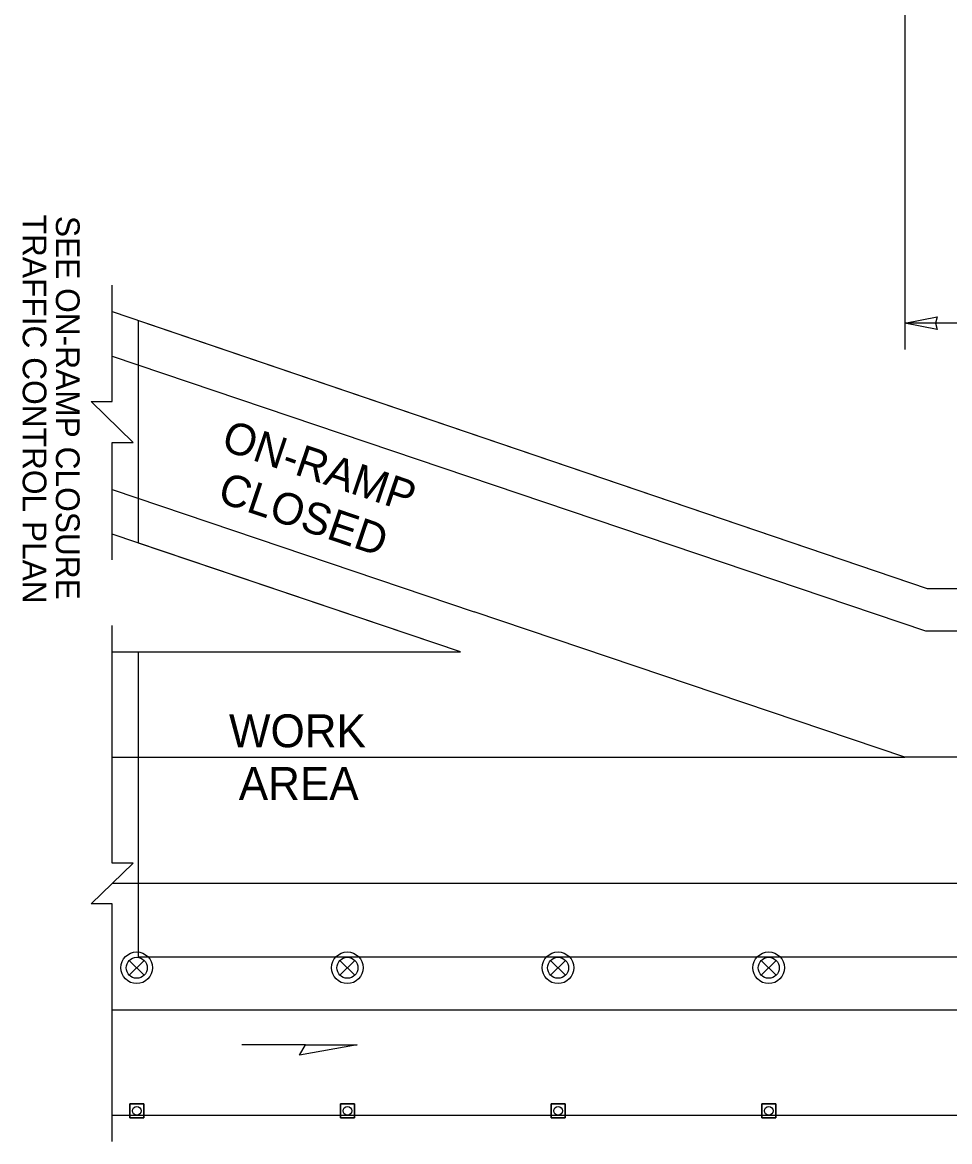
# Model space of a CAD drawing. Extents: x 99999 to 100116, y 99995 to 100013.
# Drawn here: x 100067.922 to 100070.739, y 100003.07 to 100006.47 of the extents above; entities that cross this region are included whole.
import ezdxf

# ---------------------------------------------------------------- set-up
doc = ezdxf.new("R2010")
doc.units = 0
for name, color, linetype in [('RD_MK_LineEdgeYellow', 7, 'Continuous'), ('RD_MK_LineLane', 7, 'Continuous'), ('TR_WZ_TrafficCone', 7, 'Continuous'), ('TR_WZ_TrafficSafetyDrum', 7, 'Continuous'), ('TR_WZ_WorkAreaLabel', 7, 'Continuous'), ('TR_WZ_WorkZoneDetails', 7, 'Continuous')]:
    doc.layers.add(name, color=color, linetype=linetype)

msp = doc.modelspace()

# ---------------------------------------------------------------- linework, layer by layer
at = {"layer": 'RD_MK_LineEdgeYellow'}
for p, q in [((100068.195, 100005.4562), (100070.6655, 100004.622)), ((100068.195, 100005.0509), (100069.2943, 100004.6797)), ((100070.6655, 100004.622), (100072.1758, 100004.622)), ((100068.195, 100004.238), (100069.2533, 100004.238)), ((100068.195, 100003.47), (100075.43, 100003.47))]:
    msp.add_line(p, q, dxfattribs=at)
at = {"layer": 'RD_MK_LineLane'}
for points in [[(100072.1758, 100004.238), (100070.6024, 100004.238)], [(100075.43, 100003.854), (100068.195, 100003.854)]]:
    msp.add_lwpolyline(points, dxfattribs=at)
at = {"layer": 'TR_WZ_TrafficCone'}
for points in [[(100068.2481, 100003.142), (100068.2907, 100003.142), (100068.2907, 100003.1846), (100068.2481, 100003.1846), (100068.2481, 100003.142)], [(100068.2481, 100003.1846), (100068.2907, 100003.1846), (100068.2907, 100003.142), (100068.2481, 100003.142), (100068.2481, 100003.1846)], [(100068.8881, 100003.142), (100068.9307, 100003.142), (100068.9307, 100003.1846), (100068.8881, 100003.1846), (100068.8881, 100003.142)], [(100068.8881, 100003.1846), (100068.9307, 100003.1846), (100068.9307, 100003.142), (100068.8881, 100003.142), (100068.8881, 100003.1846)], [(100069.5281, 100003.142), (100069.5707, 100003.142), (100069.5707, 100003.1846), (100069.5281, 100003.1846), (100069.5281, 100003.142)], [(100069.5281, 100003.1846), (100069.5707, 100003.1846), (100069.5707, 100003.142), (100069.5281, 100003.142), (100069.5281, 100003.1846)], [(100070.1681, 100003.142), (100070.2107, 100003.142), (100070.2107, 100003.1846), (100070.1681, 100003.1846), (100070.1681, 100003.142)], [(100070.1681, 100003.1846), (100070.2107, 100003.1846), (100070.2107, 100003.142), (100070.1681, 100003.142), (100070.1681, 100003.1846)]]:
    msp.add_lwpolyline(points, dxfattribs=at)
for centre in [(100068.2694, 100003.1633), (100068.9094, 100003.1633), (100069.5494, 100003.1633), (100070.1894, 100003.1633)]:
    msp.add_circle(centre, 0.0133, dxfattribs=at)
at = {"layer": 'TR_WZ_TrafficSafetyDrum'}
for p, q in [((100068.2468, 100003.5753), (100068.292, 100003.6206)), ((100068.292, 100003.5753), (100068.2468, 100003.6206)), ((100068.8868, 100003.5753), (100068.932, 100003.6206)), ((100068.932, 100003.5753), (100068.8868, 100003.6206)), ((100069.5268, 100003.5753), (100069.572, 100003.6206)), ((100069.572, 100003.5753), (100069.5268, 100003.6206)), ((100070.1668, 100003.5753), (100070.212, 100003.6206)), ((100070.212, 100003.5753), (100070.1668, 100003.6206))]:
    msp.add_line(p, q, dxfattribs=at)
for centre, radius in [((100068.2694, 100003.598), 0.048), ((100068.2694, 100003.598), 0.048), ((100068.9094, 100003.598), 0.048), ((100068.9094, 100003.598), 0.048), ((100069.5494, 100003.598), 0.048), ((100069.5494, 100003.598), 0.048), ((100070.1894, 100003.598), 0.048), ((100070.1894, 100003.598), 0.048), ((100068.2694, 100003.598), 0.032), ((100068.9094, 100003.598), 0.032), ((100069.5494, 100003.598), 0.032), ((100070.1894, 100003.598), 0.032)]:
    msp.add_circle(centre, radius, dxfattribs=at)
at = {"layer": 'TR_WZ_WorkZoneDetails'}
for p, q in [((100070.6024, 100008.435), (100070.6024, 100005.4763)), ((100068.195, 100005.5914), (100070.6703, 100004.75)), ((100074.4628, 100005.5563), (100070.6024, 100005.5563)), ((100069.2533, 100004.558), (100068.195, 100004.915)), ((100070.6703, 100004.75), (100072.1758, 100004.75)), ((100070.6024, 100004.238), (100069.2943, 100004.6797)), ((100068.195, 100004.558), (100069.2533, 100004.558)), ((100069.2533, 100004.238), (100070.6024, 100004.238)), ((100068.782, 100003.3639), (100068.5891, 100003.3639)), ((100068.195, 100003.15), (100075.43, 100003.15))]:
    msp.add_line(p, q, dxfattribs=at)
for points in [[(100068.195, 100004.8378), (100068.195, 100005.1943), (100068.259, 100005.1943), (100068.131, 100005.3182), (100068.195, 100005.3182), (100068.195, 100005.6714)], [(100068.195, 100003.07), (100068.195, 100003.792), (100068.131, 100003.792), (100068.259, 100003.9159), (100068.195, 100003.9159), (100068.195, 100004.638)]]:
    msp.add_lwpolyline(points, dxfattribs=at)
for points in [[(100068.275, 100003.63), (100068.275, 100004.558), (100069.2533, 100004.558), (100068.275, 100004.8881), (100068.275, 100004.8881), (100068.275, 100004.8881), (100068.275, 100005.5642), (100068.275, 100005.5642), (100068.275, 100005.5642), (100069.2641, 100005.228), (100070.6703, 100004.75), (100072.1758, 100004.75), (100072.7368, 100004.558), (100075.35, 100004.558), (100075.35, 100003.63)], [(100070.6024, 100005.5563), (100070.7007, 100005.5756), (100070.6962, 100005.5563), (100070.7007, 100005.537)], [(100068.9392, 100003.3639), (100068.7641, 100003.333), (100068.782, 100003.3639)]]:
    msp.add_lwpolyline(points, close=True, dxfattribs=at)

# ---------------------------------------------------------------- texts
at = {"layer": 'TR_WZ_WorkAreaLabel'}
for s, p in [('WORK', (100068.5496, 100004.268)), ('AREA', (100068.5793, 100004.108))]:
    msp.add_text(s, height=0.1, dxfattribs=at).set_placement(p)
at = {"layer": 'TR_WZ_WorkZoneDetails'}
for s, height, rotation, p in [('TRAFFIC CONTROL PLAN', 0.072, 270, (100067.923, 100005.8862)), ('SEE ON-RAMP CLOSURE', 0.072, 270, (100068.0238, 100005.8822)), ('ON-RAMP', 0.096, 341.341, (100068.5223, 100005.1734)), ('CLOSED', 0.096, 341.341, (100068.5108, 100005.0152))]:
    msp.add_text(s, height=height, rotation=rotation, dxfattribs=at).set_placement(p)

doc.saveas('drawing.dxf')
